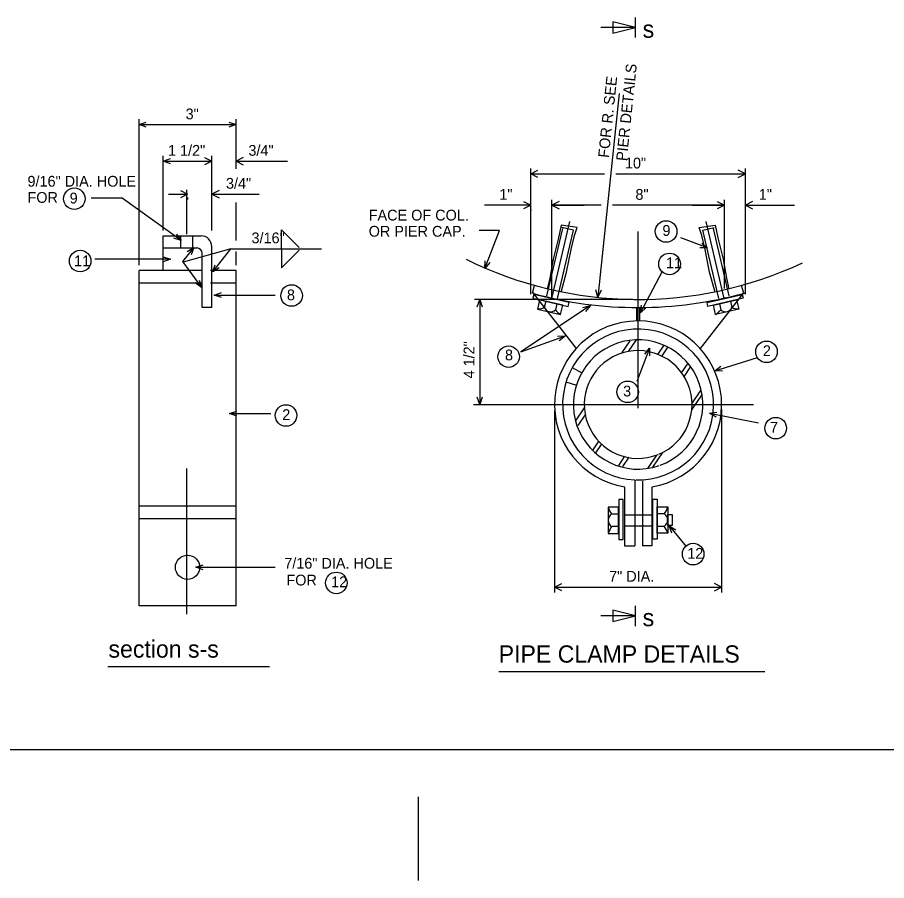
# Model space of a CAD drawing. Extents: x 15000 to 15012.1, y 999.8 to 1007.9.
# Drawn here: x 15004.734 to 15008.092, y 999.781 to 1003.118 of the extents above; entities that cross this region are included whole.
import ezdxf

# ---------------------------------------------------------------- set-up
doc = ezdxf.new("R2010")
doc.units = 0
for name, color, linetype in [('Level 1', 7, 'Continuous'), ('Level 2', 7, 'Continuous'), ('Level 37', 7, 'Continuous')]:
    doc.layers.add(name, color=color, linetype=linetype)

msp = doc.modelspace()

# ---------------------------------------------------------------- linework, layer by layer
at = {"layer": 'Level 1'}
msp.add_line((15001.0578, 1000.2885), (15011.5058, 1000.2885), dxfattribs=at)
at = {"layer": 'Level 2'}
for p, q in [((15007.1226, 1003.0404), (15007.1226, 1003.1184)), ((15007.1226, 1003.0404), (15007.1226, 1003.1184)), ((15007.1226, 1003.0794), (15006.9878, 1003.0794)), ((15007.1226, 1003.0794), (15006.9878, 1003.0794)), ((15007.0585, 1002.8241), (15006.9762, 1002.0362)), ((15005.2037, 1002.1604), (15005.2037, 1002.7244)), ((15005.2037, 1002.7036), (15005.2318, 1002.7133)), ((15005.5506, 1002.7133), (15005.5788, 1002.7036)), ((15005.5788, 1002.5328), (15005.5788, 1002.7244)), ((15005.2037, 1002.7036), (15005.5788, 1002.7036)), ((15005.2318, 1002.6938), (15005.2037, 1002.7036)), ((15005.5788, 1002.7036), (15005.5506, 1002.6938)), ((15005.2974, 1002.2948), (15005.2974, 1002.5834)), ((15005.485, 1002.2948), (15005.485, 1002.5834)), ((15005.2974, 1002.5626), (15005.3256, 1002.5723)), ((15005.2974, 1002.5626), (15005.485, 1002.5626)), ((15005.3256, 1002.5528), (15005.2974, 1002.5626)), ((15005.5788, 1002.5626), (15005.777, 1002.5626)), ((15006.7171, 1002.0488), (15006.7171, 1002.5343)), ((15006.7171, 1002.5135), (15007.0025, 1002.5135)), ((15007.0464, 1002.5135), (15007.5471, 1002.5135)), ((15007.5471, 1002.0488), (15007.5471, 1002.5343)), ((15005.3886, 1002.2806), (15005.3886, 1002.4514)), ((15005.485, 1002.4479), (15005.485, 1002.456)), ((15005.1386, 1002.4189), (15005.0189, 1002.4189)), ((15005.3663, 1002.2563), (15005.1386, 1002.4189)), ((15005.3175, 1002.4352), (15005.3913, 1002.4352)), ((15005.3913, 1002.4225), (15005.3913, 1002.4143)), ((15005.485, 1002.4352), (15005.6673, 1002.4352)), ((15006.7988, 1002.0367), (15006.7988, 1002.4131)), ((15007.4654, 1002.0698), (15007.4654, 1002.4131)), ((15007.5471, 1002.0488), (15007.5471, 1002.4131)), ((15005.5788, 1002.2563), (15005.5788, 1002.4027)), ((15006.7171, 1002.3923), (15006.5388, 1002.3923)), ((15006.7171, 1002.3756), (15006.7171, 1002.3714)), ((15006.7988, 1002.3923), (15006.9238, 1002.3923)), ((15006.9898, 1002.3923), (15006.7988, 1002.3923)), ((15007.4654, 1002.3923), (15007.0337, 1002.3923)), ((15007.3404, 1002.3923), (15007.4654, 1002.3923)), ((15007.5471, 1002.3923), (15007.736, 1002.3923)), ((15006.7992, 1002.0318), (15006.8688, 1002.3297)), ((15006.8822, 1002.2956), (15006.8379, 1002.3059)), ((15007.382, 1002.2956), (15007.4263, 1002.3059)), ((15007.465, 1002.0318), (15007.3954, 1002.3297)), ((15005.2974, 1002.2739), (15005.4433, 1002.2739)), ((15005.2974, 1002.1437), (15005.2974, 1002.2739)), ((15005.3491, 1002.2806), (15005.3663, 1002.2563)), ((15005.3655, 1002.2273), (15005.3655, 1002.2735)), ((15005.4117, 1002.2273), (15005.4117, 1002.2735)), ((15005.7541, 1002.2237), (15005.7541, 1002.2969)), ((15005.7541, 1002.2969), (15005.8224, 1002.2286)), ((15006.5969, 1002.2946), (15006.5183, 1002.2946)), ((15006.5397, 1002.1478), (15006.5969, 1002.2946)), ((15006.78, 1002.0416), (15006.841, 1002.3023)), ((15006.8206, 1002.0321), (15006.8822, 1002.2956)), ((15007.1321, 1001.6073), (15007.1321, 1002.2903)), ((15007.4436, 1002.0321), (15007.382, 1002.2956)), ((15007.4842, 1002.0416), (15007.4232, 1002.3023)), ((15005.3663, 1002.2563), (15005.3378, 1002.2647)), ((15007.4008, 1002.2271), (15007.2973, 1002.2656)), ((15007.3778, 1002.246), (15007.4008, 1002.2271)), ((15005.2974, 1002.2271), (15005.4269, 1002.2271)), ((15005.4152, 1002.2291), (15005.3718, 1002.1748)), ((15005.5588, 1002.2237), (15005.3745, 1002.1722)), ((15005.3899, 1002.2132), (15005.4152, 1002.2291)), ((15005.4152, 1002.2291), (15005.4052, 1002.201)), ((15005.4478, 1001.9973), (15005.4478, 1002.2063)), ((15005.485, 1001.9973), (15005.485, 1002.2323)), ((15005.4883, 1002.1342), (15005.5588, 1002.2237)), ((15005.5588, 1002.2237), (15005.9087, 1002.2237)), ((15005.5788, 1002.1604), (15005.5788, 1002.2128)), ((15005.7541, 1002.2237), (15005.7541, 1002.1504)), ((15005.7541, 1002.1504), (15005.8224, 1002.2188)), ((15007.4008, 1002.2271), (15007.371, 1002.2278)), ((15005.3257, 1002.183), (15005.0328, 1002.183)), ((15005.2975, 1002.1928), (15005.3257, 1002.183)), ((15005.3257, 1002.183), (15005.2975, 1002.1733)), ((15005.3718, 1002.1748), (15005.445, 1002.0745)), ((15006.5397, 1002.1478), (15006.5408, 1002.1776)), ((15006.559, 1002.1706), (15006.5397, 1002.1478)), ((15005.2037, 1000.8439), (15005.2037, 1002.1396)), ((15005.445, 1002.1396), (15005.2037, 1002.1396)), ((15005.5788, 1002.1396), (15005.4803, 1002.1396)), ((15005.4883, 1002.1342), (15005.4981, 1002.1623)), ((15005.5134, 1002.1503), (15005.4883, 1002.1342)), ((15005.5788, 1000.8439), (15005.5788, 1002.1396)), ((15007.1408, 1001.9761), (15007.2267, 1002.1372)), ((15005.4363, 1002.103), (15005.445, 1002.0745)), ((15005.445, 1002.0908), (15005.2037, 1002.0908)), ((15005.445, 1002.0745), (15005.4205, 1002.0915)), ((15005.5788, 1002.0908), (15005.4803, 1002.0908)), ((15006.7238, 1002.0519), (15006.7322, 1002.0823)), ((15007.5404, 1002.0519), (15007.532, 1002.0823)), ((15005.4938, 1002.0448), (15005.522, 1002.0545)), ((15005.4938, 1002.0448), (15005.7297, 1002.0448)), ((15005.522, 1002.035), (15005.4938, 1002.0448)), ((15006.7252, 1002.0529), (15006.8925, 1001.8383)), ((15006.9762, 1002.0362), (15006.9694, 1002.0652)), ((15006.9888, 1002.0632), (15006.9762, 1002.0362)), ((15007.539, 1002.0529), (15007.3717, 1001.8383)), ((15007.1113, 1002.028), (15006.4996, 1002.028)), ((15006.5107, 1001.9998), (15006.5204, 1002.028)), ((15006.5204, 1002.028), (15006.5204, 1001.6218)), ((15006.5204, 1002.028), (15006.5302, 1001.9998)), ((15006.9476, 1002.0048), (15006.6793, 1001.8258)), ((15006.7752, 1002.0209), (15006.7696, 1001.997)), ((15006.818, 1002.0111), (15006.8125, 1001.9873)), ((15006.9188, 1001.9973), (15006.9476, 1002.0048)), ((15006.9476, 1002.0048), (15006.9295, 1001.981)), ((15007.1408, 1001.9761), (15007.1455, 1002.0055)), ((15007.4462, 1002.0111), (15007.4517, 1001.9873)), ((15007.489, 1002.0209), (15007.4946, 1001.997)), ((15005.485, 1001.9973), (15005.4478, 1001.9973)), ((15007.1264, 1001.9957), (15007.1264, 1001.9461)), ((15007.1381, 1001.9957), (15007.1381, 1001.9461)), ((15007.1627, 1001.9963), (15007.1408, 1001.9761)), ((15006.6793, 1001.8258), (15006.851, 1001.8867)), ((15006.8212, 1001.8864), (15006.851, 1001.8867)), ((15006.851, 1001.8867), (15006.8277, 1001.8681)), ((15007.1008, 1001.8681), (15007.0698, 1001.8223)), ((15007.1245, 1001.8717), (15007.0936, 1001.8263)), ((15007.1768, 1001.8395), (15007.1275, 1001.7108)), ((15007.1577, 1001.8167), (15007.1768, 1001.8395)), ((15007.1768, 1001.8395), (15007.1758, 1001.8097)), ((15007.2318, 1001.851), (15007.2076, 1001.8153)), ((15007.2464, 1001.8441), (15007.2232, 1001.8099)), ((15007.4281, 1001.7518), (15007.5933, 1001.8028)), ((15007.3245, 1001.7813), (15007.2991, 1001.744)), ((15007.3348, 1001.7681), (15007.31, 1001.7316)), ((15007.4281, 1001.7518), (15007.4522, 1001.7694)), ((15006.878, 1001.7648), (15006.9143, 1001.7443)), ((15007.4579, 1001.7508), (15007.4281, 1001.7518)), ((15006.8533, 1001.7093), (15006.8936, 1001.6966)), ((15007.3735, 1001.6757), (15007.3387, 1001.6245)), ((15006.5204, 1001.6218), (15006.5107, 1001.6499)), ((15006.5302, 1001.6499), (15006.5204, 1001.6218)), ((15007.3796, 1001.6617), (15007.3386, 1001.6014)), ((15006.4957, 1001.6218), (15007.5782, 1001.6218)), ((15006.9243, 1001.6087), (15006.8895, 1001.5576)), ((15007.455, 1001.6029), (15007.455, 1000.895)), ((15005.5534, 1001.5864), (15005.5816, 1001.5962)), ((15005.5534, 1001.5864), (15005.7134, 1001.5864)), ((15005.5816, 1001.5767), (15005.5534, 1001.5864)), ((15006.8092, 1001.5975), (15006.8092, 1000.895)), ((15006.9293, 1001.5849), (15006.8991, 1001.5405)), ((15007.4074, 1001.588), (15007.4369, 1001.5922)), ((15007.4074, 1001.588), (15007.5974, 1001.5508)), ((15007.4332, 1001.573), (15007.4074, 1001.588)), ((15006.9803, 1001.4816), (15006.9566, 1001.4468)), ((15006.9898, 1001.4673), (15006.9675, 1001.4344)), ((15007.2258, 1001.4358), (15007.1872, 1001.379)), ((15007.0798, 1001.4218), (15007.0558, 1001.3865)), ((15007.0965, 1001.4181), (15007.0723, 1001.3824)), ((15007.2036, 1001.426), (15007.1688, 1001.3749)), ((15005.3886, 1000.8108), (15005.3886, 1001.3749)), ((15007.0802, 1001.3009), (15007.0802, 1001.0747)), ((15007.1194, 1001.3286), (15007.1194, 1001.0747)), ((15007.1496, 1001.3259), (15007.1496, 1001.0747)), ((15007.1856, 1001.3016), (15007.1856, 1001.0747)), ((15005.5788, 1001.2285), (15005.2037, 1001.2285)), ((15007.057, 1001.1983), (15007.0298, 1001.1983)), ((15007.2062, 1001.1997), (15007.2333, 1001.1997)), ((15005.5788, 1001.1797), (15005.2037, 1001.1797)), ((15007.0572, 1001.1495), (15007.0302, 1001.1495)), ((15007.206, 1001.1508), (15007.233, 1001.1508)), ((15007.2518, 1001.1528), (15007.3178, 1001.0728)), ((15007.2518, 1001.1528), (15007.2773, 1001.1373)), ((15007.2622, 1001.1248), (15007.2518, 1001.1528)), ((15007.0802, 1001.0747), (15007.1194, 1001.0747)), ((15007.1856, 1001.0747), (15007.1496, 1001.0747)), ((15005.4233, 1000.9926), (15005.4515, 1001.0023)), ((15005.4233, 1000.9926), (15005.7297, 1000.9926)), ((15005.4515, 1000.9828), (15005.4233, 1000.9926)), ((15006.8092, 1000.9158), (15007.455, 1000.9158)), ((15005.5788, 1000.8439), (15005.2037, 1000.8439)), ((15007.1226, 1000.7651), (15007.1226, 1000.8431)), ((15007.1226, 1000.8041), (15006.9878, 1000.8041)), ((15005.0836, 1000.6091), (15005.7082, 1000.6091)), ((15006.5935, 1000.5897), (15007.6222, 1000.5897))]:
    msp.add_line(p, q, dxfattribs=at)
for points in [[(15007.0347, 1003.0574), (15007.1226, 1003.0794), (15007.0347, 1003.1014)], [(15007.0347, 1003.0574), (15007.1226, 1003.0794), (15007.0347, 1003.1014)], [(15006.726, 1002.0327), (15006.8622, 1002.0008), (15006.8657, 1002.0158), (15006.7295, 1002.0476)], [(15006.726, 1002.0327), (15006.8622, 1002.0008), (15006.8657, 1002.0158), (15006.7295, 1002.0476)], [(15007.5382, 1002.0327), (15007.402, 1002.0008), (15007.3985, 1002.0158), (15007.5347, 1002.0476)], [(15007.5382, 1002.0327), (15007.402, 1002.0008), (15007.3985, 1002.0158), (15007.5347, 1002.0476)], [(15006.7434, 1001.9909), (15006.8324, 1001.9699), (15006.8408, 1002.0056), (15006.7517, 1002.0264)], [(15007.5208, 1001.9909), (15007.4318, 1001.9699), (15007.4234, 1002.0056), (15007.5125, 1002.0264)], [(15007.0573, 1001.2545), (15007.0573, 1001.0992), (15007.0743, 1001.0992), (15007.0743, 1001.2545)], [(15007.2058, 1001.2558), (15007.2058, 1001.1005), (15007.1888, 1001.1005), (15007.1888, 1001.2558)], [(15007.0165, 1001.2252), (15007.0165, 1001.1235), (15007.057, 1001.1235), (15007.057, 1001.2252)], [(15007.2467, 1001.2265), (15007.2467, 1001.1248), (15007.2062, 1001.1248), (15007.2062, 1001.2265)], [(15007.2642, 1001.1962), (15007.2642, 1001.1542), (15007.2472, 1001.1542), (15007.2472, 1001.1962)], [(15007.0347, 1000.7822), (15007.1226, 1000.8041), (15007.0347, 1000.8261)]]:
    msp.add_lwpolyline(points, close=True, dxfattribs=at)
for points in [[(15005.4573, 1002.5765), (15005.485, 1002.5626), (15005.4573, 1002.5487)], [(15005.6065, 1002.5765), (15005.5788, 1002.5626), (15005.6065, 1002.5487)], [(15006.7448, 1002.4996), (15006.7171, 1002.5135), (15006.7448, 1002.5274)], [(15007.5193, 1002.4996), (15007.5471, 1002.5135), (15007.5193, 1002.5274)], [(15005.3635, 1002.4491), (15005.3913, 1002.4352), (15005.3635, 1002.4213)], [(15005.5128, 1002.4491), (15005.485, 1002.4352), (15005.5128, 1002.4213)], [(15006.6893, 1002.4062), (15006.7171, 1002.3923), (15006.6893, 1002.3783)], [(15006.8265, 1002.4062), (15006.7988, 1002.3923), (15006.8265, 1002.3783)], [(15006.8265, 1002.4062), (15006.7988, 1002.3923), (15006.8265, 1002.3783)], [(15007.4377, 1002.4062), (15007.4654, 1002.3923), (15007.4377, 1002.3783)], [(15007.4377, 1002.4062), (15007.4654, 1002.3923), (15007.4377, 1002.3783)], [(15007.5748, 1002.4062), (15007.5471, 1002.3923), (15007.5748, 1002.3783)], [(15006.8348, 1002.0562), (15006.8556, 1002.1334), (15006.8733, 1002.2212), (15006.8859, 1002.2748), (15006.8961, 1002.3063), (15006.8345, 1002.3151), (15006.8246, 1002.2665), (15006.8038, 1002.1838), (15006.7908, 1002.1103), (15006.781, 1002.0688)], [(15007.4294, 1002.0562), (15007.4086, 1002.1334), (15007.3908, 1002.2212), (15007.3783, 1002.2748), (15007.3681, 1002.3063), (15007.4297, 1002.3151), (15007.4396, 1002.2665), (15007.4604, 1002.1838), (15007.4733, 1002.1103), (15007.4832, 1002.0688)], [(15007.1228, 1001.151), (15007.0809, 1001.151), (15007.0809, 1001.1948), (15007.1228, 1001.1948)], [(15007.1228, 1001.1948), (15007.1458, 1001.1948)], [(15007.1863, 1001.1948), (15007.1863, 1001.151), (15007.1458, 1001.151)], [(15007.1458, 1001.1948), (15007.1863, 1001.1948)], [(15007.1458, 1001.151), (15007.1228, 1001.151)], [(15006.8369, 1000.9019), (15006.8092, 1000.9158), (15006.8369, 1000.9298)], [(15007.4273, 1000.9019), (15007.455, 1000.9158), (15007.4273, 1000.9298)]]:
    msp.add_lwpolyline(points, dxfattribs=at)
for centre, radius in [((15004.9538, 1002.4173), 0.0417), ((15007.2403, 1002.2906), 0.0417), ((15004.9763, 1002.1763), 0.0417), ((15007.2537, 1002.1652), 0.0417), ((15005.7933, 1002.043), 0.0417), ((15006.6318, 1001.8066), 0.0417), ((15007.6283, 1001.8255), 0.0417), ((15007.0919, 1001.6706), 0.0417), ((15005.7717, 1001.5793), 0.0417), ((15007.6639, 1001.5302), 0.0417), ((15007.3448, 1001.0433), 0.0417), ((15005.3912, 1000.9925), 0.0469), ((15005.9661, 1000.9319), 0.0417)]:
    msp.add_circle(centre, radius, dxfattribs=at)
for centre, radius, start, end in [((15005.4433, 1002.2323), 0.0417, 0, 90), ((15005.4269, 1002.2063), 0.0208, 0, 90), ((15007.1321, 1003.528), 1.5, 243.7037, 295.0612), ((15007.1321, 1003.528), 1.5314, 254.5805, 285.571), ((15006.7465, 1002.0367), 0.0454, 266.5701, 300.7305), ((15006.7944, 1002.0065), 0.0264, 200.0458, 313.6327), ((15006.8765, 1002.0421), 0.0842, 220.6219, 238.5916), ((15007.3876, 1002.0421), 0.0842, 301.4084, 319.3781), ((15007.4697, 1002.0065), 0.0264, 226.3673, 339.9542), ((15007.5177, 1002.0367), 0.0454, 239.2695, 273.4299), ((15007.1321, 1001.6218), 0.3229, 279.5668, 260.8641), ((15007.1321, 1001.6218), 0.2917, 268.2096, 267.5112), ((15007.1321, 1001.6218), 0.25, 289.9994, 288.8965), ((15007.1321, 1001.6218), 0.2083, 292.6357, 291.6919), ((15007.0463, 1001.1739), 0.0293, 123.2073, 236.7942), ((15007.0669, 1001.2334), 0.0505, 189.7316, 223.892), ((15007.1963, 1001.2347), 0.0505, 316.108, 350.2684), ((15007.2169, 1001.1752), 0.0293, 303.2058, 56.7927), ((15007.1056, 1001.0941), 0.0936, 143.7834, 161.7531), ((15007.1576, 1001.0954), 0.0936, 18.2469, 36.2166)]:
    msp.add_arc(centre, radius, start, end, dxfattribs=at)
at = {"layer": 'Level 37'}
msp.add_line((15006.2818, 1000.1049), (15006.2818, 999.781), dxfattribs=at)

# ---------------------------------------------------------------- texts
at = {"layer": 'Level 2'}
for s, height, p in [('s', 0.0667, (15007.1497, 1003.0396)), (' 3" ', 0.04167, (15005.3683, 1002.7244)), (' 1 1/2" ', 0.04167, (15005.3003, 1002.5834)), ('3/4" ', 0.04167, (15005.6264, 1002.5834)), (' 10" ', 0.04167, (15007.0658, 1002.5343)), ('9/16" DIA. HOLE', 0.041667, (15004.7728, 1002.4639)), ('3/4" ', 0.04167, (15005.5397, 1002.456)), ('FOR', 0.04167, (15004.7728, 1002.4014)), ('9', 0.0417, (15004.9356, 1002.399)), (' 1" ', 0.04167, (15006.5805, 1002.4131)), (' 8" ', 0.04167, (15007.1063, 1002.4131)), (' 1" ', 0.04167, (15007.5831, 1002.4131)), ('FACE OF COL.', 0.041667, (15006.0912, 1002.333)), ('OR PIER CAP.', 0.041667, (15006.0912, 1002.2705)), ('9', 0.0417, (15007.2262, 1002.2738)), ('3/16"', 0.04167, (15005.6384, 1002.245)), ('11', 0.04167, (15004.9527, 1002.1562)), ('11', 0.04167, (15007.2397, 1002.1484)), ('8', 0.0417, (15005.7752, 1002.0247)), ('8', 0.0417, (15006.6178, 1001.7924)), ('2', 0.0417, (15007.6142, 1001.8087)), ('3', 0.0417, (15007.0742, 1001.6529)), ('2', 0.0417, (15005.7571, 1001.5617)), ('7', 0.0417, (15007.6415, 1001.5124)), ('12', 0.04167, (15007.3222, 1001.0255)), ('7/16" DIA. HOLE', 0.041667, (15005.7649, 1000.9872)), ('FOR', 0.04167, (15005.7731, 1000.9221)), (' 7" DIA.', 0.04167, (15007.0046, 1000.9367)), ('12', 0.04167, (15005.9462, 1000.9152)), ('s', 0.0667, (15007.1497, 1000.7644)), ('section s-s', 0.066667, (15005.0858, 1000.6431)), ('PIPE CLAMP DETAILS', 0.066667, (15006.5935, 1000.6238))]:
    msp.add_text(s, height=height, dxfattribs=at).set_placement(p)
for s, height, rotation, p in [('PIER DETAILS', 0.041667, 84.0345, (15007.0883, 1002.5615)), ('FOR R. SEE', 0.04167, 84.0345, (15007.0187, 1002.5741)), (' 4 1/2" ', 0.04167, 90, (15006.4996, 1001.7071))]:
    msp.add_text(s, height=height, rotation=rotation, dxfattribs=at).set_placement(p)

doc.saveas('drawing.dxf')
